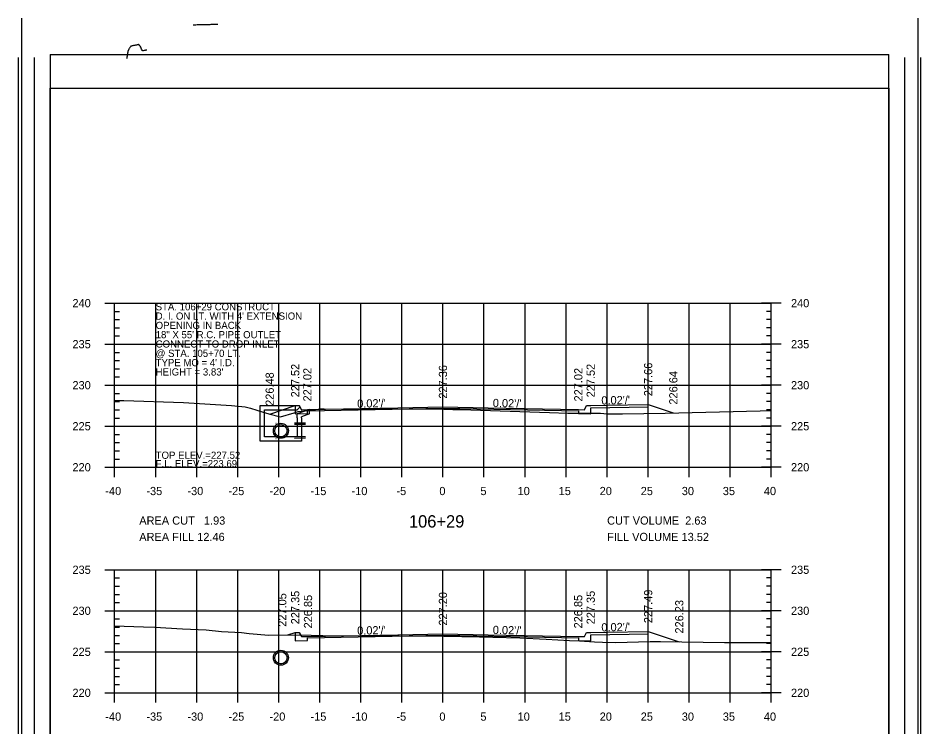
# Model space of a CAD drawing. Extents: x 1367903 to 1373764, y 376865 to 382130.
# Drawn here: x 1371165.1 to 1371385.1, y 377447.5 to 377620.4 of the extents above; entities that cross this region are included whole.
import ezdxf

# ---------------------------------------------------------------- set-up
doc = ezdxf.new("R2010")
doc.units = 0
for name, color, linetype in [('R_Axis', 7, 'Continuous'), ('R_Axis Annot', 7, 'Continuous'), ('R_Border', 7, 'Continuous'), ('R_Border PE', 7, 'Continuous'), ('R_Draft', 7, 'Continuous'), ('R_Exist Surface', 7, 'Continuous'), ('R_Fin Surface', 7, 'Continuous'), ('R_Fin Surface Annot', 7, 'Continuous'), ('R_Grid', 7, 'Continuous'), ('R_Water', 7, 'Continuous'), ('R_Water Annot', 7, 'Continuous')]:
    doc.layers.add(name, color=color, linetype=linetype)

msp = doc.modelspace()

# ---------------------------------------------------------------- linework, layer by layer
for p, q in [((1371224.13, 377525.87), (1371233.63, 377525.87)), ((1371224.13, 377522.87), (1371224.13, 377525.87)), ((1371233.8, 377525.54), (1371233.13, 377524.87)), ((1371233.8, 377525.54), (1371233.63, 377525.87)), ((1371225.13, 377522.87), (1371225.13, 377524.87)), ((1371225.13, 377524.87), (1371233.13, 377524.87)), ((1371236.13, 377524.91), (1371233.13, 377523.87)), ((1371233.13, 377522.87), (1371233.13, 377523.87)), ((1371236.13, 377523.85), (1371234.13, 377523.16)), ((1371234.13, 377522.87), (1371234.13, 377523.16))]:
    msp.add_line(p, q)
for points in [[(1371232.63, 377525.87), (1371232.63, 377525.21), (1371232.63, 377525.21), (1371232.63, 377523.84), (1371235.63, 377523.9), (1371235.63, 377524.57), (1371268.63, 377525.23), (1371301.63, 377524.57), (1371301.63, 377523.9), (1371304.63, 377523.84), (1371304.63, 377525.29), (1371318.63, 377525.57), (1371318.63, 377526.15)], [(1371236.13, 377523.85), (1371236.13, 377524.91)], [(1371232.63, 377470.54), (1371232.63, 377469.87), (1371232.63, 377469.87), (1371232.63, 377468.51), (1371235.63, 377468.57), (1371235.63, 377469.24), (1371268.63, 377469.9), (1371301.63, 377469.24), (1371301.63, 377468.57), (1371304.63, 377468.51), (1371304.63, 377469.95), (1371318.63, 377470.23), (1371318.63, 377470.82)]]:
    msp.add_lwpolyline(points)
at = {"layer": 'R_Axis'}
for p, q in [((1371186.23, 377550.84), (1371191.03, 377550.84)), ((1371188.63, 377510.84), (1371188.63, 377550.84)), ((1371351.03, 377550.84), (1371346.23, 377550.84)), ((1371348.63, 377510.84), (1371348.63, 377550.84)), ((1371188.63, 377548.84), (1371189.83, 377548.84)), ((1371348.63, 377548.84), (1371347.43, 377548.84)), ((1371188.63, 377546.84), (1371189.83, 377546.84)), ((1371188.63, 377544.84), (1371189.83, 377544.84)), ((1371348.63, 377546.84), (1371347.43, 377546.84)), ((1371348.63, 377544.84), (1371347.43, 377544.84)), ((1371188.63, 377542.84), (1371189.83, 377542.84)), ((1371348.63, 377542.84), (1371347.43, 377542.84)), ((1371186.23, 377540.84), (1371191.03, 377540.84)), ((1371351.03, 377540.84), (1371346.23, 377540.84)), ((1371188.63, 377538.84), (1371189.83, 377538.84)), ((1371348.63, 377538.84), (1371347.43, 377538.84)), ((1371188.63, 377536.84), (1371189.83, 377536.84)), ((1371348.63, 377536.84), (1371347.43, 377536.84)), ((1371188.63, 377534.84), (1371189.83, 377534.84)), ((1371348.63, 377534.84), (1371347.43, 377534.84)), ((1371188.63, 377532.84), (1371189.83, 377532.84)), ((1371348.63, 377532.84), (1371347.43, 377532.84)), ((1371186.23, 377530.84), (1371191.03, 377530.84)), ((1371351.03, 377530.84), (1371346.23, 377530.84)), ((1371188.63, 377528.84), (1371189.83, 377528.84)), ((1371348.63, 377528.84), (1371347.43, 377528.84)), ((1371188.63, 377526.84), (1371189.83, 377526.84)), ((1371348.63, 377526.84), (1371347.43, 377526.84)), ((1371188.63, 377524.84), (1371189.83, 377524.84)), ((1371188.63, 377522.84), (1371189.83, 377522.84)), ((1371348.63, 377524.84), (1371347.43, 377524.84)), ((1371348.63, 377522.84), (1371347.43, 377522.84)), ((1371186.23, 377520.84), (1371191.03, 377520.84)), ((1371351.03, 377520.84), (1371346.23, 377520.84)), ((1371188.63, 377518.84), (1371189.83, 377518.84)), ((1371348.63, 377518.84), (1371347.43, 377518.84)), ((1371188.63, 377516.84), (1371189.83, 377516.84)), ((1371348.63, 377516.84), (1371347.43, 377516.84)), ((1371188.63, 377514.84), (1371189.83, 377514.84)), ((1371348.63, 377514.84), (1371347.43, 377514.84)), ((1371188.63, 377508.44), (1371188.63, 377513.24)), ((1371188.63, 377512.84), (1371189.83, 377512.84)), ((1371198.63, 377508.44), (1371198.63, 377513.24)), ((1371208.63, 377508.44), (1371208.63, 377513.24)), ((1371218.63, 377508.44), (1371218.63, 377513.24)), ((1371228.63, 377508.44), (1371228.63, 377513.24)), ((1371238.63, 377508.44), (1371238.63, 377513.24)), ((1371248.63, 377508.44), (1371248.63, 377513.24)), ((1371258.63, 377508.44), (1371258.63, 377513.24)), ((1371268.63, 377508.44), (1371268.63, 377513.24)), ((1371278.63, 377508.44), (1371278.63, 377513.24)), ((1371288.63, 377508.44), (1371288.63, 377513.24)), ((1371298.63, 377508.44), (1371298.63, 377513.24)), ((1371308.63, 377508.44), (1371308.63, 377513.24)), ((1371318.63, 377508.44), (1371318.63, 377513.24)), ((1371328.63, 377508.44), (1371328.63, 377513.24)), ((1371338.63, 377508.44), (1371338.63, 377513.24)), ((1371348.63, 377512.84), (1371347.43, 377512.84)), ((1371348.63, 377508.44), (1371348.63, 377513.24)), ((1371186.23, 377510.84), (1371191.03, 377510.84)), ((1371188.63, 377510.84), (1371348.63, 377510.84)), ((1371351.03, 377510.84), (1371346.23, 377510.84)), ((1371186.23, 377485.84), (1371191.03, 377485.84)), ((1371188.63, 377455.84), (1371188.63, 377485.84)), ((1371351.03, 377485.84), (1371346.23, 377485.84)), ((1371348.63, 377455.84), (1371348.63, 377485.84)), ((1371188.63, 377483.84), (1371189.83, 377483.84)), ((1371348.63, 377483.84), (1371347.43, 377483.84)), ((1371188.63, 377481.84), (1371189.83, 377481.84)), ((1371348.63, 377481.84), (1371347.43, 377481.84)), ((1371188.63, 377479.84), (1371189.83, 377479.84)), ((1371348.63, 377479.84), (1371347.43, 377479.84)), ((1371188.63, 377477.84), (1371189.83, 377477.84)), ((1371348.63, 377477.84), (1371347.43, 377477.84)), ((1371186.23, 377475.84), (1371191.03, 377475.84)), ((1371351.03, 377475.84), (1371346.23, 377475.84)), ((1371188.63, 377473.84), (1371189.83, 377473.84)), ((1371348.63, 377473.84), (1371347.43, 377473.84)), ((1371188.63, 377471.84), (1371189.83, 377471.84)), ((1371348.63, 377471.84), (1371347.43, 377471.84)), ((1371188.63, 377469.84), (1371189.83, 377469.84)), ((1371188.63, 377467.84), (1371189.83, 377467.84)), ((1371348.63, 377469.84), (1371347.43, 377469.84)), ((1371348.63, 377467.84), (1371347.43, 377467.84)), ((1371186.23, 377465.84), (1371191.03, 377465.84)), ((1371351.03, 377465.84), (1371346.23, 377465.84)), ((1371188.63, 377463.84), (1371189.83, 377463.84)), ((1371348.63, 377463.84), (1371347.43, 377463.84)), ((1371188.63, 377461.84), (1371189.83, 377461.84)), ((1371348.63, 377461.84), (1371347.43, 377461.84)), ((1371188.63, 377459.84), (1371189.83, 377459.84)), ((1371348.63, 377459.84), (1371347.43, 377459.84)), ((1371188.63, 377453.44), (1371188.63, 377458.24)), ((1371188.63, 377457.84), (1371189.83, 377457.84)), ((1371198.63, 377453.44), (1371198.63, 377458.24)), ((1371208.63, 377453.44), (1371208.63, 377458.24)), ((1371218.63, 377453.44), (1371218.63, 377458.24)), ((1371228.63, 377453.44), (1371228.63, 377458.24)), ((1371238.63, 377453.44), (1371238.63, 377458.24)), ((1371248.63, 377453.44), (1371248.63, 377458.24)), ((1371258.63, 377453.44), (1371258.63, 377458.24)), ((1371268.63, 377453.44), (1371268.63, 377458.24)), ((1371278.63, 377453.44), (1371278.63, 377458.24)), ((1371288.63, 377453.44), (1371288.63, 377458.24)), ((1371298.63, 377453.44), (1371298.63, 377458.24)), ((1371308.63, 377453.44), (1371308.63, 377458.24)), ((1371318.63, 377453.44), (1371318.63, 377458.24)), ((1371328.63, 377453.44), (1371328.63, 377458.24)), ((1371338.63, 377453.44), (1371338.63, 377458.24)), ((1371348.63, 377457.84), (1371347.43, 377457.84)), ((1371348.63, 377453.44), (1371348.63, 377458.24)), ((1371186.23, 377455.84), (1371191.03, 377455.84)), ((1371188.63, 377455.84), (1371348.63, 377455.84)), ((1371351.03, 377455.84), (1371346.23, 377455.84))]:
    msp.add_line(p, q, dxfattribs=at)
at = {"layer": 'R_Border'}
for p, q in [((1371165.9, 377620.35), (1371165.9, 377279.12)), ((1371384.3, 377620.35), (1371384.3, 377279.12)), ((1371172.93, 377611.47), (1371377.26, 377611.47)), ((1371172.93, 377611.47), (1371172.93, 377280.59)), ((1371377.26, 377280.59), (1371377.26, 377611.47))]:
    msp.add_line(p, q, dxfattribs=at)
at = {"layer": 'R_Border PE'}
for p, q in [((1371165.1, 377610.76), (1371165.1, 377288.8)), ((1371169.01, 377610.76), (1371169.01, 377288.8)), ((1371381.18, 377288.8), (1371381.18, 377610.76)), ((1371385.1, 377288.8), (1371385.1, 377610.76)), ((1371172.93, 377603.25), (1371377.26, 377603.25)), ((1371172.93, 377288.8), (1371172.93, 377603.25)), ((1371377.26, 377603.25), (1371377.26, 377288.8))]:
    msp.add_line(p, q, dxfattribs=at)
for points in [[(1371209.79, 377618.69), (1371209.74, 377618.69), (1371209.46, 377618.68), (1371209.33, 377618.68), (1371209.26, 377618.67), (1371209.1, 377618.67), (1371208.75, 377618.66), (1371208.42, 377618.65), (1371207.78, 377618.63)], [(1371210.24, 377618.7), (1371209.79, 377618.69)], [(1371213.81, 377618.79), (1371213.46, 377618.78), (1371213.26, 377618.78), (1371213.1, 377618.77), (1371212.87, 377618.76), (1371212.71, 377618.76), (1371212.52, 377618.75), (1371212.27, 377618.75), (1371212.08, 377618.74), (1371211.8, 377618.73), (1371211.7, 377618.73), (1371211.65, 377618.73), (1371211.43, 377618.72), (1371211.32, 377618.72), (1371211.1, 377618.71), (1371211.02, 377618.72), (1371210.6, 377618.7), (1371210.36, 377618.7), (1371210.24, 377618.7)], [(1371196.49, 377612.54), (1371196.47, 377612.55), (1371196.45, 377612.55), (1371196.43, 377612.55), (1371196.41, 377612.55), (1371196.38, 377612.55), (1371196.35, 377612.55), (1371196.33, 377612.55), (1371196.19, 377612.51), (1371196.07, 377612.48), (1371195.8, 377612.41), (1371195.59, 377612.36), (1371195.56, 377612.35), (1371195.54, 377612.35), (1371195.52, 377612.34), (1371195.51, 377612.34), (1371195.5, 377612.35), (1371195.47, 377612.35), (1371195.45, 377612.36), (1371195.42, 377612.38), (1371195.41, 377612.39), (1371195.39, 377612.4), (1371195.37, 377612.42), (1371195.35, 377612.45), (1371195.34, 377612.47), (1371195.32, 377612.5), (1371195.3, 377612.55), (1371195.21, 377612.76), (1371195.1, 377613), (1371194.99, 377613.23), (1371194.98, 377613.26), (1371194.97, 377613.28), (1371194.93, 377613.34), (1371194.9, 377613.39), (1371194.78, 377613.57), (1371194.7, 377613.69), (1371194.67, 377613.74), (1371194.65, 377613.76), (1371194.64, 377613.78), (1371194.61, 377613.81), (1371194.6, 377613.83), (1371194.58, 377613.84), (1371194.57, 377613.85), (1371194.54, 377613.87), (1371194.53, 377613.87), (1371194.5, 377613.88), (1371194.47, 377613.88), (1371194.46, 377613.88), (1371194.42, 377613.88), (1371194.32, 377613.86), (1371194.15, 377613.82), (1371193.95, 377613.77), (1371193.81, 377613.74), (1371193.7, 377613.72), (1371193.56, 377613.69), (1371193.44, 377613.66), (1371193.26, 377613.63), (1371193.04, 377613.58), (1371193, 377613.57), (1371192.87, 377613.54), (1371192.76, 377613.52), (1371192.72, 377613.51), (1371192.69, 377613.5), (1371192.67, 377613.5), (1371192.65, 377613.49), (1371192.64, 377613.49), (1371192.62, 377613.47), (1371192.6, 377613.46), (1371192.58, 377613.44), (1371192.55, 377613.42), (1371192.52, 377613.39), (1371192.5, 377613.35), (1371192.47, 377613.31), (1371192.43, 377613.26), (1371192.37, 377613.16), (1371192.28, 377613.02), (1371192.19, 377612.89), (1371192.1, 377612.75), (1371192.05, 377612.67), (1371192.01, 377612.62), (1371191.97, 377612.55), (1371191.96, 377612.54), (1371191.95, 377612.52), (1371191.95, 377612.5), (1371191.94, 377612.48), (1371191.93, 377612.46), (1371191.93, 377612.44), (1371191.92, 377612.42), (1371191.91, 377612.39), (1371191.91, 377612.37), (1371191.9, 377612.35), (1371191.9, 377612.33), (1371191.88, 377612.24), (1371191.84, 377612), (1371191.8, 377611.76), (1371191.78, 377611.65), (1371191.69, 377611.18), (1371191.67, 377611.04), (1371191.63, 377610.84), (1371191.58, 377610.54), (1371191.55, 377610.39)]]:
    msp.add_lwpolyline(points, dxfattribs=at)
at = {"layer": 'R_Exist Surface'}
for points in [[(1371188.63, 377527.13), (1371190.84, 377527.09), (1371205.41, 377526.58), (1371217.11, 377525.88), (1371220.47, 377525.58), (1371221.77, 377525.22), (1371224.86, 377524.29), (1371226.23, 377523.84), (1371229.04, 377523.13), (1371232.34, 377524.11), (1371233.34, 377524.41), (1371238.34, 377525.03), (1371238.58, 377525.06), (1371238.89, 377525.09), (1371239.69, 377525.08), (1371268.83, 377525.01), (1371271.05, 377524.95), (1371272.95, 377524.9), (1371294.61, 377524.2), (1371299.07, 377524.02), (1371299.32, 377523.99), (1371303.07, 377524), (1371306.27, 377523.98), (1371307.03, 377524.01), (1371308.62, 377523.87), (1371312.34, 377523.85), (1371322.79, 377524.06), (1371345.95, 377524.62), (1371348.63, 377524.67)], [(1371188.63, 377472.21), (1371195.69, 377471.93), (1371198.46, 377471.82), (1371205.17, 377471.47), (1371210.95, 377471.16), (1371214.64, 377470.81), (1371219.55, 377470.51), (1371221.4, 377470.28), (1371226.22, 377469.9), (1371233.68, 377469.96), (1371239.33, 377469.84), (1371254.01, 377469.74), (1371257.97, 377469.71), (1371268.88, 377469.67), (1371277.54, 377469.47), (1371280.8, 377469.37), (1371287.39, 377469.21), (1371293.76, 377468.91), (1371299.48, 377468.61), (1371301.88, 377468.52), (1371305.58, 377468.25), (1371307.53, 377468.17), (1371310.69, 377468.12), (1371319.15, 377468.32), (1371321.6, 377468.36), (1371337.26, 377468.14), (1371348.63, 377468.14)]]:
    msp.add_lwpolyline(points, dxfattribs=at)
at = {"layer": 'R_Fin Surface'}
for points in [[(1371226.41, 377523.8), (1371232.63, 377525.87), (1371233.63, 377525.87), (1371234.13, 377524.87), (1371235.63, 377524.9), (1371257.63, 377525.34), (1371268.63, 377525.56), (1371279.63, 377525.34), (1371301.63, 377524.9), (1371303.13, 377524.87), (1371303.63, 377525.87), (1371304.63, 377525.87), (1371308.63, 377525.95), (1371318.63, 377526.15), (1371324.76, 377524.11)], [(1371230.82, 377469.94), (1371232.63, 377470.54), (1371233.63, 377470.54), (1371234.13, 377469.54), (1371235.63, 377469.57), (1371257.63, 377470.01), (1371268.63, 377470.23), (1371279.63, 377470.01), (1371301.63, 377469.57), (1371303.13, 377469.54), (1371303.63, 377470.54), (1371304.63, 377470.54), (1371308.63, 377470.62), (1371318.63, 377470.82), (1371326.21, 377468.29)]]:
    msp.add_lwpolyline(points, dxfattribs=at)
at = {"layer": 'R_Grid'}
for p, q in [((1371188.63, 377550.84), (1371348.63, 377550.84)), ((1371188.63, 377510.84), (1371188.63, 377550.84)), ((1371198.63, 377510.84), (1371198.63, 377550.84)), ((1371208.63, 377510.84), (1371208.63, 377550.84)), ((1371218.63, 377510.84), (1371218.63, 377550.84)), ((1371228.63, 377510.84), (1371228.63, 377550.84)), ((1371238.63, 377510.84), (1371238.63, 377550.84)), ((1371248.63, 377510.84), (1371248.63, 377550.84)), ((1371258.63, 377510.84), (1371258.63, 377550.84)), ((1371268.63, 377510.84), (1371268.63, 377550.84)), ((1371278.63, 377510.84), (1371278.63, 377550.84)), ((1371288.63, 377510.84), (1371288.63, 377550.84)), ((1371298.63, 377510.84), (1371298.63, 377550.84)), ((1371308.63, 377510.84), (1371308.63, 377550.84)), ((1371318.63, 377510.84), (1371318.63, 377550.84)), ((1371328.63, 377510.84), (1371328.63, 377550.84)), ((1371338.63, 377510.84), (1371338.63, 377550.84)), ((1371348.63, 377510.84), (1371348.63, 377550.84)), ((1371188.63, 377540.84), (1371348.63, 377540.84)), ((1371188.63, 377530.84), (1371348.63, 377530.84)), ((1371188.63, 377520.84), (1371348.63, 377520.84)), ((1371188.63, 377510.84), (1371348.63, 377510.84)), ((1371188.63, 377485.84), (1371348.63, 377485.84)), ((1371188.63, 377455.84), (1371188.63, 377485.84)), ((1371198.63, 377455.84), (1371198.63, 377485.84)), ((1371208.63, 377455.84), (1371208.63, 377485.84)), ((1371218.63, 377455.84), (1371218.63, 377485.84)), ((1371228.63, 377455.84), (1371228.63, 377485.84)), ((1371238.63, 377455.84), (1371238.63, 377485.84)), ((1371248.63, 377455.84), (1371248.63, 377485.84)), ((1371258.63, 377455.84), (1371258.63, 377485.84)), ((1371268.63, 377455.84), (1371268.63, 377485.84)), ((1371278.63, 377455.84), (1371278.63, 377485.84)), ((1371288.63, 377455.84), (1371288.63, 377485.84)), ((1371298.63, 377455.84), (1371298.63, 377485.84)), ((1371308.63, 377455.84), (1371308.63, 377485.84)), ((1371318.63, 377455.84), (1371318.63, 377485.84)), ((1371328.63, 377455.84), (1371328.63, 377485.84)), ((1371338.63, 377455.84), (1371338.63, 377485.84)), ((1371348.63, 377455.84), (1371348.63, 377485.84)), ((1371188.63, 377475.84), (1371348.63, 377475.84)), ((1371188.63, 377465.84), (1371348.63, 377465.84)), ((1371188.63, 377455.84), (1371348.63, 377455.84))]:
    msp.add_line(p, q, dxfattribs=at)
at = {"layer": 'R_Water'}
for p, q in [((1371227.93, 377521.55), (1371227.98, 377521.55)), ((1371227.93, 377521.22), (1371227.98, 377521.22)), ((1371235.11, 377521.57), (1371232.45, 377521.55)), ((1371235.11, 377521.23), (1371232.45, 377521.22)), ((1371227.93, 377518.22), (1371227.98, 377518.22)), ((1371227.93, 377517.88), (1371227.98, 377517.88)), ((1371235.11, 377518.23), (1371232.45, 377518.22)), ((1371235.11, 377517.9), (1371232.45, 377517.88)), ((1371229.13, 377466.24), (1371229.13, 377466.2)), ((1371229.13, 377465.91), (1371229.13, 377465.86)), ((1371229.13, 377462.91), (1371229.13, 377462.86)), ((1371229.13, 377462.58), (1371229.13, 377462.53))]:
    msp.add_line(p, q, dxfattribs=at)
for points in [[(1371234.13, 377522.87), (1371234.13, 377517.22), (1371229.13, 377517.22), (1371224.13, 377517.22), (1371224.13, 377522.87)], [(1371233.13, 377522.87), (1371233.13, 377518.22), (1371229.13, 377518.22), (1371225.13, 377518.22), (1371225.13, 377522.87)]]:
    msp.add_lwpolyline(points, dxfattribs=at)
for centre, radius in [((1371229.13, 377519.72), 1.83), ((1371229.13, 377519.72), 1.83), ((1371229.13, 377519.72), 1.5), ((1371229.13, 377519.72), 1.5), ((1371229.13, 377464.39), 1.83), ((1371229.13, 377464.39), 1.5)]:
    msp.add_circle(centre, radius, dxfattribs=at)

# ---------------------------------------------------------------- texts
at = {"layer": 'R_Axis Annot'}
for s, height, p in [('240', 2, (1371178.35, 377549.84)), ('240', 2, (1371353.43, 377549.84)), ('235', 2, (1371178.35, 377539.84)), ('235', 2, (1371353.43, 377539.84)), ('230', 2, (1371178.35, 377529.84)), ('230', 2, (1371353.43, 377529.84)), ('225', 2, (1371178.35, 377519.84)), ('225', 2, (1371353.43, 377519.84)), ('220', 2, (1371178.35, 377509.84)), ('220', 2, (1371353.43, 377509.84)), ('-40', 2, (1371186.36, 377504.04)), ('-35', 2, (1371196.36, 377504.04)), ('-30', 2, (1371206.36, 377504.04)), ('-25', 2, (1371216.36, 377504.04)), ('-20', 2, (1371226.36, 377504.04)), ('-15', 2, (1371236.36, 377504.04)), ('-10', 2, (1371246.36, 377504.04)), ('-5', 2, (1371257.29, 377504.04)), ('0', 2, (1371267.76, 377504.04)), ('5', 2, (1371277.75, 377504.04)), ('10', 2, (1371286.82, 377504.04)), ('15', 2, (1371296.82, 377504.04)), ('20', 2, (1371306.82, 377504.04)), ('25', 2, (1371316.82, 377504.04)), ('30', 2, (1371326.82, 377504.04)), ('35', 2, (1371336.82, 377504.04)), ('40', 2, (1371346.82, 377504.04)), ('AREA CUT   1.93', 2, (1371194.63, 377496.84)), ('106+29', 3, (1371260.34, 377496.14)), ('CUT VOLUME  2.63', 2, (1371308.63, 377496.84)), ('AREA FILL 12.46', 2, (1371194.63, 377492.84)), ('FILL VOLUME 13.52', 2, (1371308.63, 377492.84)), ('235', 2, (1371178.35, 377484.84)), ('235', 2, (1371353.43, 377484.84)), ('230', 2, (1371178.35, 377474.84)), ('230', 2, (1371353.43, 377474.84)), ('225', 2, (1371178.35, 377464.84)), ('225', 2, (1371353.43, 377464.84)), ('220', 2, (1371178.35, 377454.84)), ('220', 2, (1371353.43, 377454.84)), ('-40', 2, (1371186.36, 377449.04)), ('-35', 2, (1371196.36, 377449.04)), ('-30', 2, (1371206.36, 377449.04)), ('-25', 2, (1371216.36, 377449.04)), ('-20', 2, (1371226.36, 377449.04)), ('-15', 2, (1371236.36, 377449.04)), ('-10', 2, (1371246.36, 377449.04)), ('-5', 2, (1371257.29, 377449.04)), ('0', 2, (1371267.76, 377449.04)), ('5', 2, (1371277.75, 377449.04)), ('10', 2, (1371286.82, 377449.04)), ('15', 2, (1371296.82, 377449.04)), ('20', 2, (1371306.82, 377449.04)), ('25', 2, (1371316.82, 377449.04)), ('30', 2, (1371326.82, 377449.04)), ('35', 2, (1371336.82, 377449.04)), ('40', 2, (1371346.82, 377449.04))]:
    msp.add_text(s, height=height, dxfattribs=at).set_placement(p)
at = {"layer": 'R_Draft'}
for s, p in [('STA. 106+29 CONSTRUCT', (1371198.63, 377549.09)), ("D. I. ON LT. WITH 4' EXTENSION", (1371198.63, 377546.82)), ('OPENING IN BACK', (1371198.63, 377544.55)), ('18" X 55\' R.C. PIPE OUTLET', (1371198.63, 377542.28)), ('CONNECT TO DROP INLET', (1371198.63, 377540.01)), ('@ STA. 105+70 LT.', (1371198.63, 377537.74)), ("TYPE MO = 4' I.D.", (1371198.63, 377535.47)), ("HEIGHT = 3.83'", (1371198.63, 377533.2))]:
    msp.add_text(s, height=1.75, dxfattribs=at).set_placement(p)
at = {"layer": 'R_Fin Surface Annot'}
for s, rotation, p in [('227.66', 90, (1371319.63, 377528.15)), ('226.48', 90, (1371227.41, 377525.8)), ('227.52', 90, (1371233.63, 377527.87)), ('227.02', 90, (1371236.59, 377526.87)), ('227.36', 90, (1371269.63, 377527.56)), ('227.02', 90, (1371302.61, 377526.87)), ('227.52', 90, (1371305.63, 377527.87)), ('226.64', 90, (1371325.76, 377526.11)), ("0.02'/'", 1.1458, (1371247.75, 377525.34)), ("0.02'/'", 358.8542, (1371280.76, 377525.52)), ("0.02'/'", 1.1458, (1371307.25, 377526.12)), ('227.05', 90, (1371230.48, 377471.94)), ('227.35', 90, (1371233.63, 377472.54)), ('226.85', 90, (1371236.75, 377471.54)), ('227.20', 90, (1371269.63, 377472.23)), ('226.85', 90, (1371302.58, 377471.54)), ('227.35', 90, (1371305.63, 377472.54)), ('227.49', 90, (1371319.63, 377472.82)), ('226.23', 90, (1371327.21, 377470.29)), ("0.02'/'", 1.1458, (1371247.75, 377470.01)), ("0.02'/'", 358.8542, (1371280.76, 377470.19)), ("0.02'/'", 1.1458, (1371307.25, 377470.79))]:
    msp.add_text(s, height=2, rotation=rotation, dxfattribs=at).set_placement(p)
at = {"layer": 'R_Water Annot'}
for s, p in [('TOP ELEV.=227.52', (1371198.63, 377512.89)), ('F.L. ELEV.=223.69', (1371198.63, 377510.84))]:
    msp.add_text(s, height=1.75, dxfattribs=at).set_placement(p)

doc.saveas('drawing.dxf')
